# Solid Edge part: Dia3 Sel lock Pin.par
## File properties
Title: Dia3 Sel lock Pin
Author: Dan
Template: Normal.par
Last saved by: Dan
Revision: 7
Application: Solid Edge
Density: 0 kg/mm^3
Accuracy: 0.99
Document Number: P52-021
Project Name: Piston Pump P52
Material: steel
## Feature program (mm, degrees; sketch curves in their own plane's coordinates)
sketch for "unnamed Protrusion 1" plane through (0, 0, 0) normal (0, 0, 1) x-axis (1, 0, 0)
  circle centre (0, 0) radius 1.6
extrude "unnamed Protrusion 1" add finite 14 symmetric
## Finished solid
Body 1: solid body, 3 faces, 2 edges, 0 vertices.
  Faces by surface: plane 2, cylinder 1
  Edges by curve: circle 2
Bounding box of the edges (mm): 3.200 x 3.200 x 14.000, from (-1.6, -1.6, -7) to (1.6, 1.6, 7).
Cylindrical faces by radius (mm): R1.6 x1
Planar faces by outward normal: +z 1, -z 1
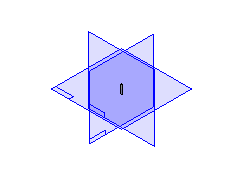
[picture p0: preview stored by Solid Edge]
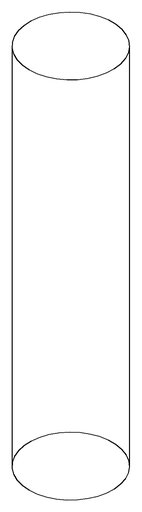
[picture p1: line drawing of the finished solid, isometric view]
